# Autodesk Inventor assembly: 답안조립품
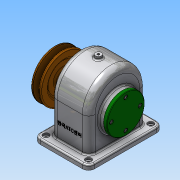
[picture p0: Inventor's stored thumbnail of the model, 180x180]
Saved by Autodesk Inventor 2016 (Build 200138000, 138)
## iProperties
Created: 2018-08
Part Number: 답안조립품
Material: 일반
Document SubType Name: Assembly
Designer: Administrator
Author: Administrator
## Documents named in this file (14)
- C:\Users\Administrator\Desktop\480811V1001\답안조립품.iam
- C:\Users\Administrator\Desktop\480811V1001\본체.ipt
- C:\Users\Administrator\Desktop\480811V1001\뒤커버.ipt
- C:\Users\Administrator\Desktop\480811V1001\베어링 6203.ipt
- C:\Users\Administrator\Desktop\480811V1001\축.ipt
- C:\Users\Administrator\Desktop\480811V1001\키 6x6x22.ipt
- C:\Users\Administrator\Desktop\480811V1001\스퍼기어.ipt
- C:\Users\Administrator\Desktop\480811V1001\앞커버.ipt
- C:\Users\Administrator\Desktop\480811V1001\부시.ipt
- C:\Users\Administrator\Desktop\480811V1001\오일 실 28 40 8.ipt
- C:\Users\Administrator\Desktop\480811V1001\키 5x5x18.ipt
- C:\Users\Administrator\Desktop\480811V1001\V-벨트풀리.ipt
- C:\Users\Administrator\Desktop\480811V1001\멈춤나사 M4.ipt
- C:\Users\Administrator\Desktop\480811V1001\볼트 M4.ipt
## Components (1 placed, 1 different names)
1. V-벨트풀리:1
